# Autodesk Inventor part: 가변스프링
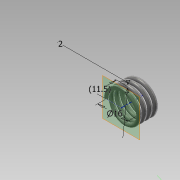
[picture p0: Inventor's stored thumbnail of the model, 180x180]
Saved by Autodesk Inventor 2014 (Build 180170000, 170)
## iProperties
Created: 2015-04
Part Number: 가변스프링
Material: 강철, 탄소
Document SubType Name: Modeling
Designer: Administrator
Density: 7.87 g/cm^3
Appearance: 반연마
Mass: 4.78768 g
Surface Area: 12.5241 cm^2
Volume: 0.608346 cm^3
Author: Administrator
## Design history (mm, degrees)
sketch "스케치1"
  geometry: L1 (0, 0)-(-8, 0); L2 (-8, 0)-(-8, -11.5); L3 (-8, -11.5)-(0, -11.5); L4 (0, -11.5)-(0, 0); C1 r 1 at (-8, 0)
  constraints: 8 end point, 2 parallel, 1 centre point, 1 coincident, 1 horizontal, 1 perpendicular
  dimensions: "d0" = 2 diameter of C1; "d1" = 11.50049 distance between parallel lines of L3 L1 (derived); "d2" = 16 diameter of L2 L4
feature "코일1" pitch "d3" = 10; turns "d5" = 4; dims "d4" = 11.50049 (= d1), "d6" = 0, angle "d7" = 90 deg, angle "d8" = 90 deg, "d9" = 0, "d10" = 0
sketch "스케치2"
  geometry: L1 (7, 0)-(9, 0) reference; 1 further point
  constraints: 1 horizontal alignment
extrude "돌출1" cut sketch "스케치2" stored distance "d11" = 10; taper "d12" = 0 deg
node "작업 평면1"
sketch "스케치3"
  geometry: L1 (9, 0)-(7, 0) reference; 1 further point
  constraints: 1 horizontal alignment
extrude "돌출2" cut sketch "스케치3" stored distance "d13" = 10; taper "d14" = 0 deg
node "솔리드1"
node "절단 모서리 투영1"
node "절단 모서리 투영2"
